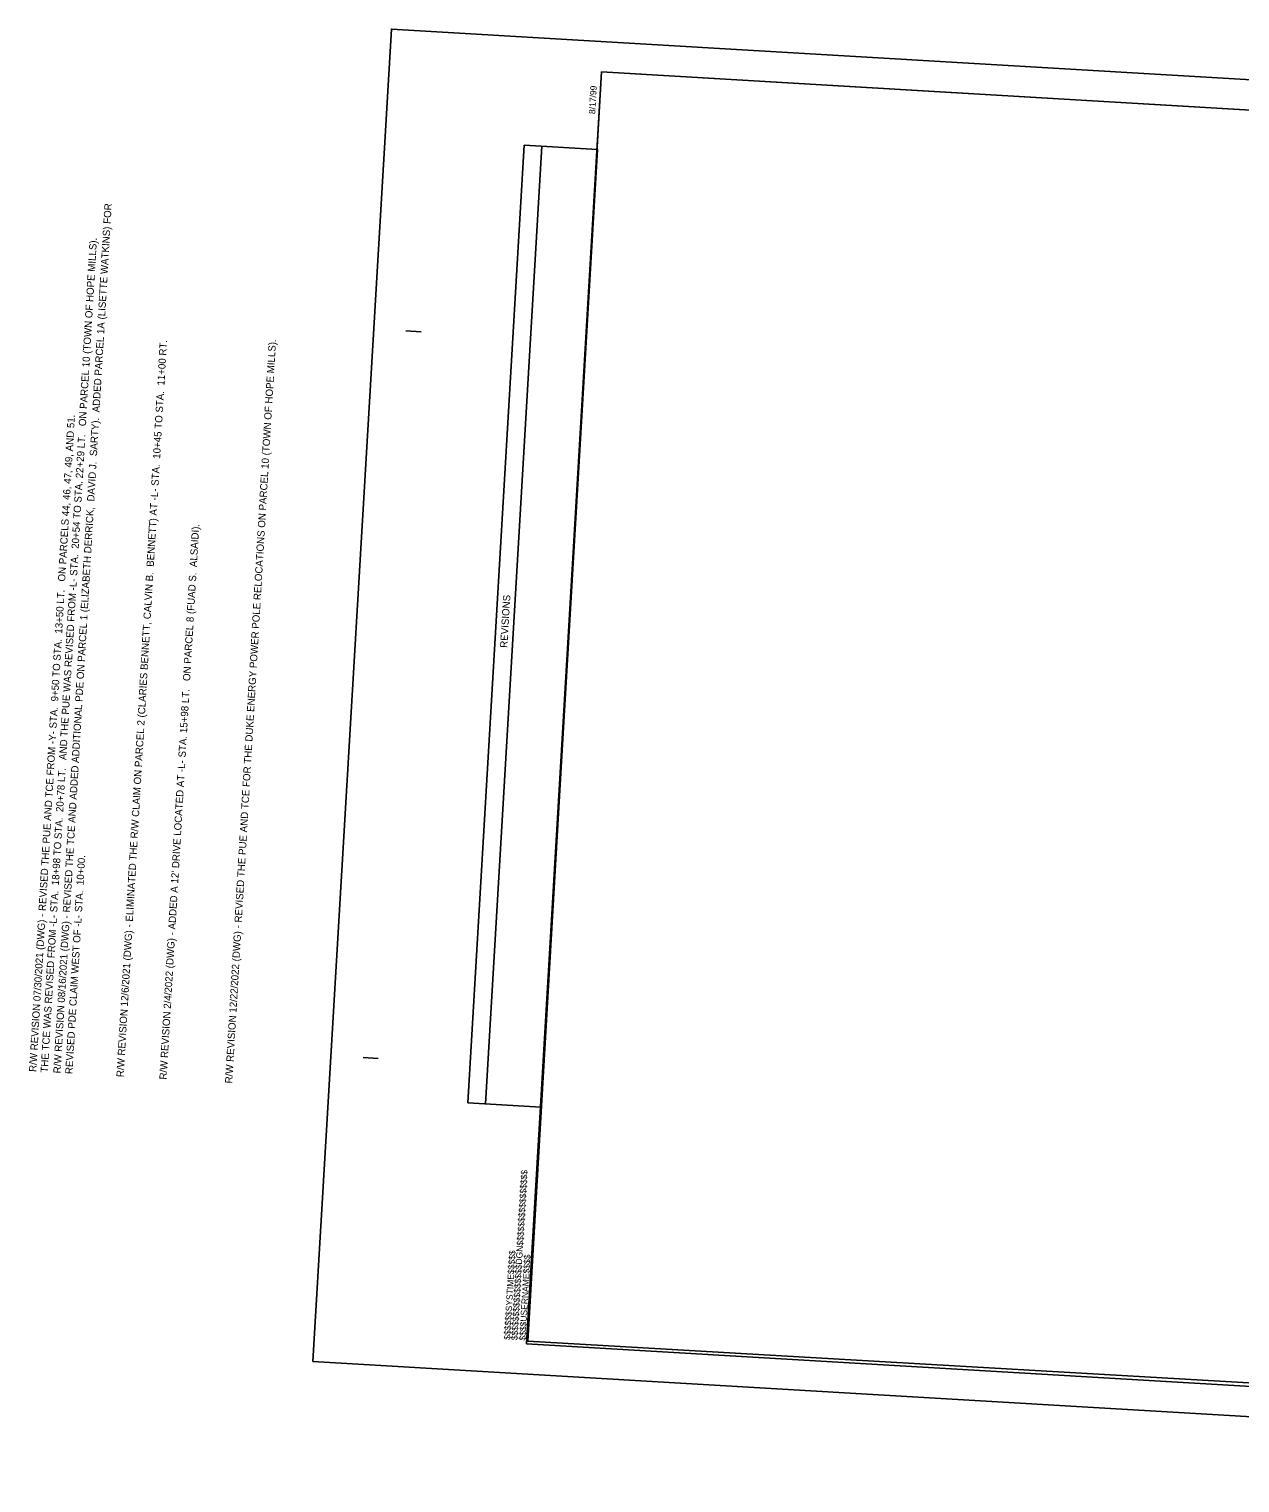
# Model space of a CAD drawing. Extents: x 2010737 to 2012732, y 444258 to 445456.
# Drawn here: x 2010737 to 2011735, y 444258 to 445456 of the extents above; entities that cross this region are included whole.
import ezdxf

# ---------------------------------------------------------------- set-up
doc = ezdxf.new("R2010")
doc.units = 0
for name, color, linetype in [('Old_Level_1', 7, 'Continuous'), ('Sheet Block Revision CELL', 7, 'Continuous'), ('Sheet Block System Information CELL', 7, 'Continuous'), ('Sheet Clip Boundary CELL', 7, 'Continuous'), ('Sheet Plan And Profile CELL', 7, 'Continuous'), ('Sheet Plot Border Outside CELL', 7, 'Continuous')]:
    doc.layers.add(name, color=color, linetype=linetype)

msp = doc.modelspace()

# ---------------------------------------------------------------- linework, layer by layer
at = {"layer": 'Sheet Block Revision CELL'}
msp.add_line((2011112.7, 444570.6), (2011159.2, 445359.8), dxfattribs=at)
msp.add_lwpolyline([(2011098.2, 444571.4), (2011144.7, 445360.7), (2011205.1, 445357.1), (2011158.6, 444567.9)], close=True, dxfattribs=at)
at = {"layer": 'Sheet Block System Information CELL'}
msp.add_line((2011146.7, 444372.9), (2011146.7, 444372.9), dxfattribs=at)
at = {"layer": 'Sheet Clip Boundary CELL'}
msp.add_lwpolyline([(2011771.6, 445387.9), (2011477.9, 445405.2), (2011208.5, 445421.1), (2011200.1, 445278.3), (2011147.8, 444375), (2012145.7, 444317.5)], dxfattribs=at)
at = {"layer": 'Sheet Plan And Profile CELL'}
for p, q in [((2011047.2, 445207.7), (2011059.7, 445207)), ((2011011.9, 444608.8), (2011024.3, 444608)), ((2011146.7, 444372.9), (2011146.7, 444372.9)), ((2011146.7, 444372.9), (2011146.7, 444372.9)), ((2011146.7, 444372.9), (2011146.7, 444372.9)), ((2011146.7, 444372.9), (2011146.7, 444372.9)), ((2011146.7, 444372.9), (2011146.7, 444372.9))]:
    msp.add_line(p, q, dxfattribs=at)
msp.add_lwpolyline([(2012705.9, 445332.8), (2011208.5, 445421.1), (2011146.7, 444372.9), (2012644.1, 444284.7)], close=True, dxfattribs=at)
at = {"layer": 'Sheet Plot Border Outside CELL'}
msp.add_lwpolyline([(2010970.6, 444358.3), (2012667.6, 444258.2), (2012732.3, 445356.3), (2011035.3, 445456.4)], close=True, dxfattribs=at)

# ---------------------------------------------------------------- texts
at = {"layer": 'Old_Level_1'}
for s, p in [('R/W REVISION 08/16/2021 (DWG) - REVISED THE TCE AND ADDED ADDITIONAL PDE ON PARCEL 1 (ELIZABETH DERRICK,  DAVID J.  SARTY).  ADDED PARCEL 1A (LISETTE WATKINS) FOR   ', (2010762.6, 444595.6)), ('THE TCE WAS REVISED FROM -L- STA.  18+98 TO STA.  20+78 LT.   AND THE PUE WAS REVISED FROM -L- STA.  20+54 TO STA. 22+29 LT.   ON PARCEL 10 (TOWN OF HOPE MILLS). ', (2010752.1, 444596.2)), ('R/W REVISION 12/6/2021 (DWG) - ELIMINATED THE R/W CLAIM ON PARCEL 2 (CLARIES BENNETT, CALVIN B.  BENNETT) AT -L- STA.  10+45 TO STA.  11+00 RT. ', (2010814.6, 444592.5)), ('R/W REVISION 12/22/2022 (DWG) - REVISED THE PUE AND TCE FOR THE DUKE ENERGY POWER POLE RELOCATIONS ON PARCEL 10 (TOWN OF HOPE MILLS).', (2010904.1, 444587.3)), ('R/W REVISION 07/30/2021 (DWG) - REVISED THE PUE AND TCE FROM -Y- STA.  9+50 TO STA.  13+50 LT.   ON PARCELS 44, 46, 47, 49, AND 51. ', (2010742.6, 444596.8)), ("R/W REVISION 2/4/2022 (DWG) - ADDED A 12' DRIVE LOCATED AT -L- STA. 15+98 LT.   ON PARCEL 8 (FUAD S.  ALSAIDI).", (2010850, 444590.5)), ('REVISED PDE CLAIM WEST OF -L- STA.  10+00. ', (2010772.4, 444595))]:
    msp.add_text(s, height=6, rotation=86.6264, dxfattribs=at).set_placement(p)
at = {"layer": 'Sheet Block Revision CELL'}
msp.add_text('REVISIONS', height=6, rotation=86.6264, dxfattribs=at).set_placement((2011130.8, 444946.3))
at = {"layer": 'Sheet Block System Information CELL'}
for s, p in [('$$$$$$$$$$$$$$$$DGN$$$$$$$$$$$$$$$$', (2011139.2, 444375.7)), ('$$$$$$SYSTIME$$$$$', (2011133.2, 444376.1)), ('$$$$USERNAME$$$$', (2011145.8, 444375.4))]:
    msp.add_text(s, height=5.25, rotation=86.6264, dxfattribs=at).set_placement(p)
at = {"layer": 'Sheet Plan And Profile CELL'}
msp.add_text('8/17/99', height=5.25, rotation=86.6264, dxfattribs=at).set_placement((2011203.2, 445386.2))

doc.saveas('drawing.dxf')
